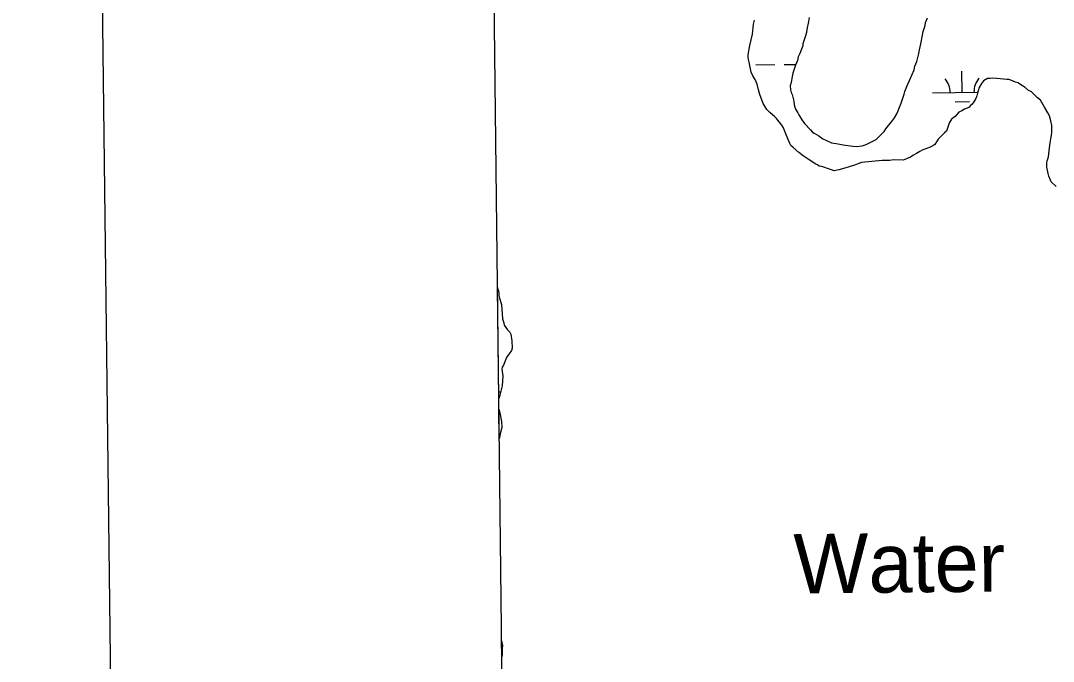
# Model space of a CAD drawing. Extents: x 3702978 to 3741108, y 397120 to 422907.
# Drawn here: x 3706319 to 3708060, y 409118 to 410197 of the extents above; entities that cross this region are included whole.
import ezdxf

# ---------------------------------------------------------------- set-up
doc = ezdxf.new("R2010")
doc.units = 0
for name, color, linetype in [('V-ANNO-SYMB', 7, 'Continuous'), ('V-GRID-FRAM', 7, 'Continuous'), ('V-RIVR-IDEN', 7, 'Continuous'), ('V-TOPO-SHOR', 7, 'Continuous'), ('V-WETL-SWMP', 7, 'Continuous')]:
    doc.layers.add(name, color=color, linetype=linetype)

msp = doc.modelspace()

# ---------------------------------------------------------------- linework, layer by layer
at = {"layer": 'V-ANNO-SYMB'}
msp.add_lwpolyline([(3706603.518, 398362.242), (3739684.166, 398773.175), (3739399.517, 421687.983), (3706318.867, 421277.049), (3706603.518, 398362.242)], dxfattribs=at)
at = {"layer": 'V-GRID-FRAM'}
msp.add_lwpolyline([(3706994.144, 420708.381), (3738756.065, 421094.145), (3738984.817, 402913.159), (3707207.029, 402527.202), (3706994.144, 420708.381)], dxfattribs=at)
at = {"layer": 'V-TOPO-SHOR'}
for p, q in [((3707552.633, 410174.373), (3707554.371, 410191.441)), ((3707554.371, 410191.441), (3707555.611, 410198.278)), ((3707646.974, 410195.83), (3707643.812, 410182.143)), ((3707648.214, 410202.667), (3707646.974, 410195.83)), ((3707843.361, 410189.134), (3707843.957, 410193.915)), ((3707843.957, 410193.915), (3707847.217, 410202.151)), ((3707548.207, 410155.212), (3707552.633, 410174.373)), ((3707643.217, 410177.362), (3707641.307, 410169.832)), ((3707643.812, 410182.143), (3707643.217, 410177.362)), ((3707836.418, 410158.342), (3707838.886, 410172.698)), ((3707838.886, 410172.698), (3707840.139, 410178.853)), ((3707840.139, 410178.853), (3707843.361, 410189.134)), ((3707545.082, 410139.482), (3707548.207, 410155.212)), ((3707637.489, 410154.77), (3707634.862, 410149.271)), ((3707641.307, 410169.832), (3707637.428, 410158.177)), ((3707637.428, 410158.177), (3707637.489, 410154.77)), ((3707833.876, 410148.074), (3707836.418, 410158.342)), ((3707545.155, 410135.394), (3707545.082, 410139.482)), ((3707632.271, 410141.728), (3707629.644, 410136.229)), ((3707634.862, 410149.271), (3707632.271, 410141.728)), ((3707829.462, 410128.232), (3707832.624, 410141.918)), ((3707832.624, 410141.918), (3707833.876, 410148.074)), ((3707545.897, 410132), (3707545.155, 410135.394)), ((3707546.664, 410127.243), (3707545.897, 410132)), ((3707550.376, 410110.273), (3707546.664, 410127.243)), ((3707625.12, 410122.519), (3707623.174, 410117.032)), ((3707628.391, 410130.074), (3707625.12, 410122.519)), ((3707629.644, 410136.229), (3707628.391, 410130.074)), ((3707824.938, 410114.521), (3707826.191, 410120.677)), ((3707826.191, 410120.677), (3707829.462, 410128.232)), ((3707553.211, 410104.19), (3707550.376, 410110.273)), ((3707556.728, 410098.12), (3707553.211, 410104.19)), ((3707619.331, 410103.333), (3707617.471, 410093.077)), ((3707620.595, 410108.808), (3707619.331, 410103.333)), ((3707623.174, 410117.032), (3707620.595, 410108.808)), ((3707817.081, 410096.661), (3707824.938, 410114.521)), ((3707560.281, 410090.006), (3707556.728, 410098.12)), ((3707562.496, 410080.505), (3707560.281, 410090.006)), ((3707617.471, 410093.077), (3707616.206, 410087.603)), ((3707616.206, 410087.603), (3707616.328, 410080.79)), ((3707809.236, 410078.12), (3707812.496, 410086.357)), ((3707812.496, 410086.357), (3707814.466, 410090.481)), ((3707814.466, 410090.481), (3707817.081, 410096.661)), ((3707938.481, 410091.345), (3707934.515, 410084.459)), ((3707941.801, 410096.175), (3707938.481, 410091.345)), ((3707948.553, 410099.703), (3707941.801, 410096.175)), ((3707953.322, 410099.789), (3707948.553, 410099.703)), ((3707957.397, 410100.544), (3707953.322, 410099.789)), ((3707964.222, 410099.985), (3707957.397, 410100.544)), ((3707981.29, 410098.247), (3707964.222, 410099.985)), ((3707984.696, 410098.308), (3707981.29, 410098.247)), ((3707988.127, 410097.007), (3707984.696, 410098.308)), ((3707995.682, 410093.735), (3707988.127, 410097.007)), ((3708000.476, 410092.458), (3707995.682, 410093.735)), ((3708003.237, 410090.463), (3708000.476, 410092.458)), ((3708012.204, 410084.491), (3708003.237, 410090.463)), ((3707564.674, 410073.048), (3707562.496, 410080.505)), ((3707570.406, 410057.477), (3707564.674, 410073.048)), ((3707616.328, 410080.79), (3707617.776, 410076.046)), ((3707617.776, 410076.046), (3707619.2, 410072.664)), ((3707619.2, 410072.664), (3707622.121, 410061.813)), ((3707802.778, 410058.241), (3707807.959, 410073.327)), ((3707807.959, 410073.327), (3707809.236, 410078.12)), ((3707930.672, 410070.76), (3707928.714, 410065.954)), ((3707931.961, 410074.872), (3707930.672, 410070.76)), ((3707932.569, 410078.972), (3707931.961, 410074.872)), ((3707934.515, 410084.459), (3707932.569, 410078.972)), ((3708017.74, 410079.82), (3708012.204, 410084.491)), ((3708022.557, 410077.18), (3708017.74, 410079.82)), ((3708032.96, 410067.145), (3708022.557, 410077.18)), ((3707576.721, 410047.368), (3707570.406, 410057.477)), ((3707622.121, 410061.813), (3707622.912, 410055.693)), ((3707622.912, 410055.693), (3707623.667, 410051.618)), ((3707623.667, 410051.618), (3707625.09, 410048.236)), ((3707798.242, 410045.212), (3707800.175, 410051.38)), ((3707800.175, 410051.38), (3707802.778, 410058.241)), ((3707917.39, 410051.44), (3707913.339, 410049.323)), ((3707920.066, 410054.214), (3707917.39, 410051.44)), ((3707922.754, 410056.307), (3707920.066, 410054.214)), ((3707925.406, 410060.443), (3707922.754, 410056.307)), ((3707928.714, 410065.954), (3707925.406, 410060.443)), ((3708037.802, 410063.143), (3708032.96, 410067.145)), ((3708044.823, 410051.684), (3708037.802, 410063.143)), ((3708050.444, 410042.244), (3708044.823, 410051.684)), ((3707581.575, 410042.685), (3707576.721, 410047.368)), ((3707589.885, 410035.337), (3707581.575, 410042.685)), ((3707592.659, 410032.661), (3707589.885, 410035.337)), ((3707601.723, 410021.239), (3707592.659, 410032.661)), ((3707625.09, 410048.236), (3707628.607, 410042.166)), ((3707628.607, 410042.166), (3707630.712, 410038.796)), ((3707630.712, 410038.796), (3707635.64, 410030.026)), ((3707786.99, 410026.61), (3707791.637, 410033.508)), ((3707791.637, 410033.508), (3707795.602, 410040.394)), ((3707795.602, 410040.394), (3707798.242, 410045.212)), ((3707893.814, 410036.024), (3707887.769, 410031.145)), ((3707900.505, 410042.959), (3707893.814, 410036.024)), ((3707905.237, 410045.088), (3707900.505, 410042.959)), ((3707909.957, 410047.899), (3707905.237, 410045.088)), ((3707913.339, 410049.323), (3707909.957, 410047.899)), ((3708053.267, 410036.843), (3708050.444, 410042.244)), ((3708055.458, 410028.704), (3708053.267, 410036.843)), ((3707604.534, 410016.519), (3707601.723, 410021.239)), ((3707606.651, 410012.468), (3707604.534, 410016.519)), ((3707635.64, 410030.026), (3707639.837, 410023.968)), ((3707639.837, 410023.968), (3707650.252, 410013.251)), ((3707776.979, 410014.845), (3707786.99, 410026.61)), ((3707881.87, 410018.091), (3707879.267, 410011.229)), ((3707883.147, 410022.884), (3707881.87, 410018.091)), ((3707884.46, 410025.634), (3707883.147, 410022.884)), ((3707887.769, 410031.145), (3707884.46, 410025.634)), ((3708056.967, 410020.553), (3708055.458, 410028.704)), ((3708057.175, 410008.972), (3708056.967, 410020.553)), ((3707608.805, 410006.373), (3707606.651, 410012.468)), ((3707615.23, 409990.133), (3707608.805, 410006.373)), ((3707650.252, 410013.251), (3707653.732, 410009.224)), ((3707653.732, 410009.224), (3707656.481, 410007.911)), ((3707656.481, 410007.911), (3707664.061, 410003.277)), ((3707664.061, 410003.277), (3707670.971, 409997.949)), ((3707670.971, 409997.949), (3707675.777, 409995.991)), ((3707760.947, 409996.838), (3707774.328, 410010.708)), ((3707774.328, 410010.708), (3707776.979, 410014.845)), ((3707875.91, 410008.443), (3707865.205, 409997.347)), ((3707879.267, 410011.229), (3707875.91, 410008.443)), ((3708054.086, 409991.198), (3708055.327, 409998.035)), ((3708055.327, 409998.035), (3708056.579, 410004.191)), ((3708056.579, 410004.191), (3708057.175, 410008.972)), ((3707617.335, 409986.763), (3707615.23, 409990.133)), ((3707620.802, 409983.418), (3707617.335, 409986.763)), ((3707630.487, 409975.414), (3707620.802, 409983.418)), ((3707675.777, 409995.991), (3707685.4, 409991.393)), ((3707685.4, 409991.393), (3707693.6, 409990.177)), ((3707693.6, 409990.177), (3707699.756, 409988.925)), ((3707699.756, 409988.925), (3707705.218, 409988.341)), ((3707705.218, 409988.341), (3707721.617, 409985.91)), ((3707721.617, 409985.91), (3707727.08, 409985.326)), ((3707727.08, 409985.326), (3707737.286, 409986.191)), ((3707737.286, 409986.191), (3707744.062, 409988.357)), ((3707744.062, 409988.357), (3707760.947, 409996.838)), ((3707851.812, 409984.159), (3707838.272, 409979.145)), ((3707856.544, 409986.288), (3707851.812, 409984.159)), ((3707859.914, 409988.393), (3707856.544, 409986.288)), ((3707865.205, 409997.347), (3707859.914, 409988.393)), ((3708051.096, 409967.974), (3708052.871, 409982.998)), ((3708052.871, 409982.998), (3708054.086, 409991.198)), ((3707638.091, 409969.418), (3707630.487, 409975.414)), ((3707647.751, 409962.776), (3707638.091, 409969.418)), ((3707811.96, 409964.362), (3707806.547, 409962.22)), ((3707818.724, 409967.209), (3707811.96, 409964.362)), ((3707822.762, 409970.007), (3707818.724, 409967.209)), ((3707828.833, 409973.524), (3707822.762, 409970.007)), ((3707834.222, 409977.028), (3707828.833, 409973.524)), ((3707838.272, 409979.145), (3707834.222, 409977.028)), ((3708049.175, 409961.124), (3708051.096, 409967.974)), ((3707659.467, 409955.49), (3707647.751, 409962.776)), ((3707662.216, 409954.177), (3707659.467, 409955.49)), ((3707664.978, 409952.182), (3707662.216, 409954.177)), ((3707669.078, 409951.574), (3707664.978, 409952.182)), ((3707682.108, 409947.037), (3707669.078, 409951.574)), ((3707685.538, 409945.736), (3707682.108, 409947.037)), ((3707690.332, 409944.459), (3707685.538, 409945.736)), ((3707697.801, 409945.956), (3707690.332, 409944.459)), ((3707707.971, 409948.865), (3707697.801, 409945.956)), ((3707724.236, 409953.927), (3707707.971, 409948.865)), ((3707736.425, 409958.235), (3707724.236, 409953.927)), ((3707771.121, 409961.584), (3707736.425, 409958.235)), ((3707784.065, 409961.816), (3707771.121, 409961.584)), ((3707790.184, 409962.608), (3707784.065, 409961.816)), ((3707806.547, 409962.22), (3707790.184, 409962.608)), ((3708048.554, 409957.706), (3708049.175, 409961.124)), ((3708048.689, 409950.212), (3708048.554, 409957.706)), ((3708050.916, 409940.03), (3708048.689, 409950.212)), ((3708051.683, 409935.273), (3708050.916, 409940.03)), ((3708054.531, 409928.509), (3708051.683, 409935.273)), ((3708055.942, 409925.809), (3708054.531, 409928.509)), ((3708064.264, 409917.78), (3708055.942, 409925.809)), ((3707122.485, 409747.6), (3707122.796, 409746.861)), ((3707122.796, 409746.861), (3707124.244, 409742.117)), ((3707124.244, 409742.117), (3707124.999, 409738.041)), ((3707124.999, 409738.041), (3707125.072, 409733.954)), ((3707125.072, 409733.954), (3707128.005, 409722.421)), ((3707128.005, 409722.421), (3707129.429, 409719.039)), ((3707129.429, 409719.039), (3707131.22, 409695.219)), ((3707131.22, 409695.219), (3707133.386, 409688.444)), ((3707133.386, 409688.444), (3707134.14, 409684.368)), ((3707134.14, 409684.368), (3707139.737, 409676.291)), ((3707139.737, 409676.291), (3707143.217, 409672.264)), ((3707143.217, 409672.264), (3707145.322, 409668.895)), ((3707145.322, 409668.895), (3707146.88, 409658.019)), ((3707146.88, 409658.019), (3707147.1, 409645.756)), ((3707139.827, 409633.359), (3707137.844, 409629.916)), ((3707142.503, 409636.133), (3707139.827, 409633.359)), ((3707146.492, 409641.656), (3707142.503, 409636.133)), ((3707147.1, 409645.756), (3707146.492, 409641.656)), ((3707132.626, 409616.874), (3707130.644, 409613.431)), ((3707137.844, 409629.916), (3707132.626, 409616.874)), ((3707130.644, 409613.431), (3707130.024, 409610.013)), ((3707130.024, 409610.013), (3707131.582, 409599.137)), ((3707131.582, 409599.137), (3707130.525, 409582.081)), ((3707130.525, 409582.081), (3707128.604, 409575.231)), ((3707126.074, 409564.282), (3707124.672, 409560.84)), ((3707128.604, 409575.231), (3707126.074, 409564.282)), ((3707124.885, 409542.633), (3707126.576, 409536.35)), ((3707126.576, 409536.35), (3707129.558, 409522.093)), ((3707129.741, 409511.874), (3707127.212, 409500.925)), ((3707129.558, 409522.093), (3707129.741, 409511.874)), ((3707126.592, 409497.506), (3707125.47, 409492.65)), ((3707127.212, 409500.925), (3707126.592, 409497.506))]:
    msp.add_line(p, q, dxfattribs=at)
at = {"layer": 'V-WETL-SWMP'}
for p, q in [((3707552.633, 410174.373), (3707554.371, 410191.441)), ((3707554.371, 410191.441), (3707555.611, 410198.278)), ((3707646.974, 410195.83), (3707643.812, 410182.143)), ((3707648.214, 410202.667), (3707646.974, 410195.83)), ((3707843.361, 410189.134), (3707843.957, 410193.915)), ((3707843.957, 410193.915), (3707847.217, 410202.151)), ((3707548.207, 410155.212), (3707552.633, 410174.373)), ((3707643.217, 410177.362), (3707641.307, 410169.832)), ((3707643.812, 410182.143), (3707643.217, 410177.362)), ((3707836.418, 410158.342), (3707838.886, 410172.698)), ((3707838.886, 410172.698), (3707840.139, 410178.853)), ((3707840.139, 410178.853), (3707843.361, 410189.134)), ((3707545.082, 410139.482), (3707548.207, 410155.212)), ((3707637.489, 410154.77), (3707634.862, 410149.271)), ((3707641.307, 410169.832), (3707637.428, 410158.177)), ((3707637.428, 410158.177), (3707637.489, 410154.77)), ((3707833.876, 410148.074), (3707836.418, 410158.342)), ((3707545.155, 410135.394), (3707545.082, 410139.482)), ((3707632.271, 410141.728), (3707629.644, 410136.229)), ((3707634.862, 410149.271), (3707632.271, 410141.728)), ((3707829.462, 410128.232), (3707832.624, 410141.918)), ((3707832.624, 410141.918), (3707833.876, 410148.074)), ((3707545.897, 410132), (3707545.155, 410135.394)), ((3707546.664, 410127.243), (3707545.897, 410132)), ((3707550.376, 410110.273), (3707546.664, 410127.243)), ((3707557.854, 410122.762), (3707589.852, 410123.159)), ((3707605.851, 410123.358), (3707625.589, 410123.603)), ((3707625.12, 410122.519), (3707623.174, 410117.032)), ((3707628.391, 410130.074), (3707625.12, 410122.519)), ((3707629.644, 410136.229), (3707628.391, 410130.074)), ((3707824.938, 410114.521), (3707826.191, 410120.677)), ((3707826.191, 410120.677), (3707829.462, 410128.232)), ((3707553.211, 410104.19), (3707550.376, 410110.273)), ((3707556.728, 410098.12), (3707553.211, 410104.19)), ((3707619.331, 410103.333), (3707617.471, 410093.077)), ((3707620.595, 410108.808), (3707619.331, 410103.333)), ((3707623.174, 410117.032), (3707620.595, 410108.808)), ((3707817.081, 410096.661), (3707824.938, 410114.521)), ((3707905.774, 410076.338), (3707905.327, 410112.335)), ((3707560.281, 410090.006), (3707556.728, 410098.12)), ((3707562.496, 410080.505), (3707560.281, 410090.006)), ((3707617.471, 410093.077), (3707616.206, 410087.603)), ((3707616.206, 410087.603), (3707616.328, 410080.79)), ((3707809.236, 410078.12), (3707812.496, 410086.357)), ((3707812.496, 410086.357), (3707814.466, 410090.481)), ((3707814.466, 410090.481), (3707817.081, 410096.661)), ((3707938.481, 410091.345), (3707934.515, 410084.459)), ((3707941.801, 410096.175), (3707938.481, 410091.345)), ((3707948.553, 410099.703), (3707941.801, 410096.175)), ((3707953.322, 410099.789), (3707948.553, 410099.703)), ((3707957.397, 410100.544), (3707953.322, 410099.789)), ((3707964.222, 410099.985), (3707957.397, 410100.544)), ((3707981.29, 410098.247), (3707964.222, 410099.985)), ((3707984.696, 410098.308), (3707981.29, 410098.247)), ((3707988.127, 410097.007), (3707984.696, 410098.308)), ((3707995.682, 410093.735), (3707988.127, 410097.007)), ((3708000.476, 410092.458), (3707995.682, 410093.735)), ((3708003.237, 410090.463), (3708000.476, 410092.458)), ((3708012.204, 410084.491), (3708003.237, 410090.463)), ((3707564.674, 410073.048), (3707562.496, 410080.505)), ((3707570.406, 410057.477), (3707564.674, 410073.048)), ((3707616.328, 410080.79), (3707617.776, 410076.046)), ((3707617.776, 410076.046), (3707619.2, 410072.664)), ((3707619.2, 410072.664), (3707622.121, 410061.813)), ((3707802.778, 410058.241), (3707807.959, 410073.327)), ((3707807.959, 410073.327), (3707809.236, 410078.12)), ((3707855.778, 410075.717), (3707932.227, 410076.666)), ((3707930.672, 410070.76), (3707928.714, 410065.954)), ((3707931.961, 410074.872), (3707930.672, 410070.76)), ((3707932.569, 410078.972), (3707931.961, 410074.872)), ((3707934.515, 410084.459), (3707932.569, 410078.972)), ((3708017.74, 410079.82), (3708012.204, 410084.491)), ((3708022.557, 410077.18), (3708017.74, 410079.82)), ((3708032.96, 410067.145), (3708022.557, 410077.18)), ((3707576.721, 410047.368), (3707570.406, 410057.477)), ((3707622.121, 410061.813), (3707622.912, 410055.693)), ((3707622.912, 410055.693), (3707623.667, 410051.618)), ((3707623.667, 410051.618), (3707625.09, 410048.236)), ((3707798.242, 410045.212), (3707800.175, 410051.38)), ((3707800.175, 410051.38), (3707802.778, 410058.241)), ((3707893.967, 410060.759), (3707917.965, 410061.057)), ((3707917.39, 410051.44), (3707913.339, 410049.323)), ((3707920.066, 410054.214), (3707917.39, 410051.44)), ((3707922.754, 410056.307), (3707920.066, 410054.214)), ((3707925.406, 410060.443), (3707922.754, 410056.307)), ((3707928.714, 410065.954), (3707925.406, 410060.443)), ((3708037.802, 410063.143), (3708032.96, 410067.145)), ((3708044.823, 410051.684), (3708037.802, 410063.143)), ((3708050.444, 410042.244), (3708044.823, 410051.684)), ((3707581.575, 410042.685), (3707576.721, 410047.368)), ((3707589.885, 410035.337), (3707581.575, 410042.685)), ((3707592.659, 410032.661), (3707589.885, 410035.337)), ((3707601.723, 410021.239), (3707592.659, 410032.661)), ((3707625.09, 410048.236), (3707628.607, 410042.166)), ((3707628.607, 410042.166), (3707630.712, 410038.796)), ((3707630.712, 410038.796), (3707635.64, 410030.026)), ((3707786.99, 410026.61), (3707791.637, 410033.508)), ((3707791.637, 410033.508), (3707795.602, 410040.394)), ((3707795.602, 410040.394), (3707798.242, 410045.212)), ((3707893.814, 410036.024), (3707887.769, 410031.145)), ((3707900.505, 410042.959), (3707893.814, 410036.024)), ((3707905.237, 410045.088), (3707900.505, 410042.959)), ((3707909.957, 410047.899), (3707905.237, 410045.088)), ((3707913.339, 410049.323), (3707909.957, 410047.899)), ((3708053.267, 410036.843), (3708050.444, 410042.244)), ((3708055.458, 410028.704), (3708053.267, 410036.843)), ((3707604.534, 410016.519), (3707601.723, 410021.239)), ((3707606.651, 410012.468), (3707604.534, 410016.519)), ((3707635.64, 410030.026), (3707639.837, 410023.968)), ((3707639.837, 410023.968), (3707650.252, 410013.251)), ((3707776.979, 410014.845), (3707786.99, 410026.61)), ((3707881.87, 410018.091), (3707879.267, 410011.229)), ((3707883.147, 410022.884), (3707881.87, 410018.091)), ((3707884.46, 410025.634), (3707883.147, 410022.884)), ((3707887.769, 410031.145), (3707884.46, 410025.634)), ((3708056.967, 410020.553), (3708055.458, 410028.704)), ((3708057.175, 410008.972), (3708056.967, 410020.553)), ((3707608.805, 410006.373), (3707606.651, 410012.468)), ((3707615.23, 409990.133), (3707608.805, 410006.373)), ((3707650.252, 410013.251), (3707653.732, 410009.224)), ((3707653.732, 410009.224), (3707656.481, 410007.911)), ((3707656.481, 410007.911), (3707664.061, 410003.277)), ((3707664.061, 410003.277), (3707670.971, 409997.949)), ((3707670.971, 409997.949), (3707675.777, 409995.991)), ((3707760.947, 409996.838), (3707774.328, 410010.708)), ((3707774.328, 410010.708), (3707776.979, 410014.845)), ((3707875.91, 410008.443), (3707865.205, 409997.347)), ((3707879.267, 410011.229), (3707875.91, 410008.443)), ((3708054.086, 409991.198), (3708055.327, 409998.035)), ((3708055.327, 409998.035), (3708056.579, 410004.191)), ((3708056.579, 410004.191), (3708057.175, 410008.972)), ((3707617.335, 409986.763), (3707615.23, 409990.133)), ((3707620.802, 409983.418), (3707617.335, 409986.763)), ((3707630.487, 409975.414), (3707620.802, 409983.418)), ((3707675.777, 409995.991), (3707685.4, 409991.393)), ((3707685.4, 409991.393), (3707693.6, 409990.177)), ((3707693.6, 409990.177), (3707699.756, 409988.925)), ((3707699.756, 409988.925), (3707705.218, 409988.341)), ((3707705.218, 409988.341), (3707721.617, 409985.91)), ((3707721.617, 409985.91), (3707727.08, 409985.326)), ((3707727.08, 409985.326), (3707737.286, 409986.191)), ((3707737.286, 409986.191), (3707744.062, 409988.357)), ((3707744.062, 409988.357), (3707760.947, 409996.838)), ((3707851.812, 409984.159), (3707838.272, 409979.145)), ((3707856.544, 409986.288), (3707851.812, 409984.159)), ((3707859.914, 409988.393), (3707856.544, 409986.288)), ((3707865.205, 409997.347), (3707859.914, 409988.393)), ((3708051.096, 409967.974), (3708052.871, 409982.998)), ((3708052.871, 409982.998), (3708054.086, 409991.198)), ((3707638.091, 409969.418), (3707630.487, 409975.414)), ((3707647.751, 409962.776), (3707638.091, 409969.418)), ((3707811.96, 409964.362), (3707806.547, 409962.22)), ((3707818.724, 409967.209), (3707811.96, 409964.362)), ((3707822.762, 409970.007), (3707818.724, 409967.209)), ((3707828.833, 409973.524), (3707822.762, 409970.007)), ((3707834.222, 409977.028), (3707828.833, 409973.524)), ((3707838.272, 409979.145), (3707834.222, 409977.028)), ((3708049.175, 409961.124), (3708051.096, 409967.974)), ((3707659.467, 409955.49), (3707647.751, 409962.776)), ((3707662.216, 409954.177), (3707659.467, 409955.49)), ((3707664.978, 409952.182), (3707662.216, 409954.177)), ((3707669.078, 409951.574), (3707664.978, 409952.182)), ((3707682.108, 409947.037), (3707669.078, 409951.574)), ((3707685.538, 409945.736), (3707682.108, 409947.037)), ((3707690.332, 409944.459), (3707685.538, 409945.736)), ((3707697.801, 409945.956), (3707690.332, 409944.459)), ((3707707.971, 409948.865), (3707697.801, 409945.956)), ((3707724.236, 409953.927), (3707707.971, 409948.865)), ((3707736.425, 409958.235), (3707724.236, 409953.927)), ((3707771.121, 409961.584), (3707736.425, 409958.235)), ((3707784.065, 409961.816), (3707771.121, 409961.584)), ((3707790.184, 409962.608), (3707784.065, 409961.816)), ((3707806.547, 409962.22), (3707790.184, 409962.608)), ((3708048.554, 409957.706), (3708049.175, 409961.124)), ((3708048.689, 409950.212), (3708048.554, 409957.706)), ((3708050.916, 409940.03), (3708048.689, 409950.212)), ((3708051.683, 409935.273), (3708050.916, 409940.03)), ((3708054.531, 409928.509), (3708051.683, 409935.273)), ((3708055.942, 409925.809), (3708054.531, 409928.509)), ((3708064.264, 409917.78), (3708055.942, 409925.809)), ((3707124.672, 409560.84), (3707122.485, 409747.6)), ((3707122.485, 409747.6), (3707122.796, 409746.861)), ((3707122.796, 409746.861), (3707124.244, 409742.117)), ((3707124.244, 409742.117), (3707124.999, 409738.041)), ((3707124.999, 409738.041), (3707125.072, 409733.954)), ((3707125.072, 409733.954), (3707128.005, 409722.421)), ((3707128.005, 409722.421), (3707129.429, 409719.039)), ((3707129.429, 409719.039), (3707131.22, 409695.219)), ((3707131.22, 409695.219), (3707133.386, 409688.444)), ((3707133.386, 409688.444), (3707134.14, 409684.368)), ((3707134.14, 409684.368), (3707139.737, 409676.291)), ((3707139.737, 409676.291), (3707143.217, 409672.264)), ((3707143.217, 409672.264), (3707145.322, 409668.895)), ((3707145.322, 409668.895), (3707146.88, 409658.019)), ((3707146.88, 409658.019), (3707147.1, 409645.756)), ((3707139.827, 409633.359), (3707137.844, 409629.916)), ((3707142.503, 409636.133), (3707139.827, 409633.359)), ((3707146.492, 409641.656), (3707142.503, 409636.133)), ((3707147.1, 409645.756), (3707146.492, 409641.656)), ((3707132.626, 409616.874), (3707130.644, 409613.431)), ((3707137.844, 409629.916), (3707132.626, 409616.874)), ((3707130.644, 409613.431), (3707130.024, 409610.013)), ((3707130.024, 409610.013), (3707131.582, 409599.137)), ((3707131.582, 409599.137), (3707130.525, 409582.081)), ((3707130.525, 409582.081), (3707128.604, 409575.231)), ((3707124.54, 409572.058), (3707127.88, 409572.1)), ((3707126.074, 409564.282), (3707124.672, 409560.84)), ((3707128.604, 409575.231), (3707126.074, 409564.282)), ((3707125.47, 409492.65), (3707124.885, 409542.633)), ((3707124.885, 409542.633), (3707126.576, 409536.35)), ((3707126.576, 409536.35), (3707129.558, 409522.093)), ((3707129.741, 409511.874), (3707127.212, 409500.925)), ((3707129.558, 409522.093), (3707129.741, 409511.874)), ((3707126.592, 409497.506), (3707125.47, 409492.65)), ((3707127.212, 409500.925), (3707126.592, 409497.506)), ((3707129.766, 409125.782), (3707129.455, 409152.292)), ((3707129.455, 409152.292), (3707130.884, 409144.574)), ((3707129.766, 409125.782), (3707129.455, 409152.292)), ((3707129.455, 409152.292), (3707130.884, 409144.574)), ((3707130.484, 409128.893), (3707129.766, 409125.782)), ((3707130.484, 409128.893), (3707129.766, 409125.782)), ((3707130.884, 409144.574), (3707130.288, 409139.793)), ((3707130.884, 409144.574), (3707130.288, 409139.793)), ((3707130.288, 409139.793), (3707130.484, 409128.893)), ((3707130.288, 409139.793), (3707130.484, 409128.893))]:
    msp.add_line(p, q, dxfattribs=at)
for centre, start, end in [((3707850.529, 410076.126), 359.939883, 41.483542), ((3707961.007, 410077.499), 139.93988, 181.483539)]:
    msp.add_arc(centre, 35.246, start, end, dxfattribs=at)

# ---------------------------------------------------------------- texts
at = {"layer": 'V-RIVR-IDEN'}
msp.add_text('Water', height=99.9998, rotation=0.572928, dxfattribs=at).set_placement((3707622.048, 409232.133))

doc.saveas('drawing.dxf')
